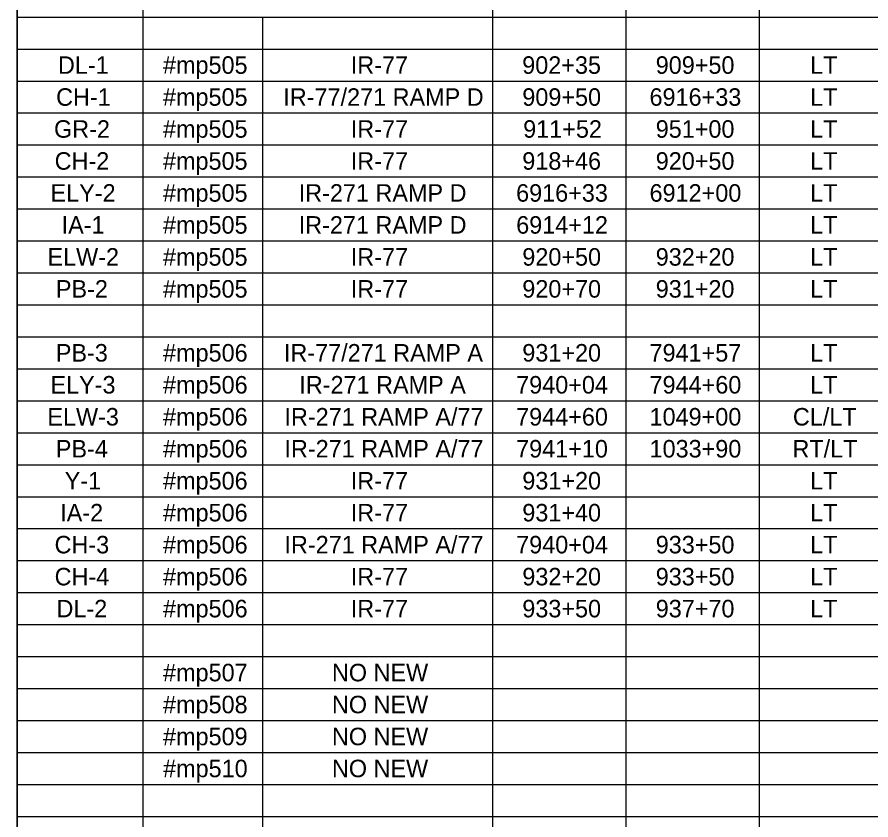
# Model space of a CAD drawing. Extents: x 91011267 to 91022583, y 37007614 to 37014266.
# Drawn here: x 91014537.6 to 91014904.6, y 37008137 to 37008481.9 of the extents above; entities that cross this region are included whole.
import ezdxf

# ---------------------------------------------------------------- set-up
doc = ezdxf.new("R2010")
doc.units = 0
doc.layers.add('SC_Scratch2', color=7, linetype='Continuous')
doc.layers.add('SH_Data', color=7, linetype='Continuous')

msp = doc.modelspace()

# ---------------------------------------------------------------- linework, layer by layer
at = {"layer": 'SC_Scratch2'}
msp.add_lwpolyline([(91014537.63, 37008663.81), (91016062.63, 37008663.81), (91016062.63, 37007613.81), (91014537.63, 37007613.81)], close=True, dxfattribs=at)
at = {"layer": 'SH_Data'}
for p, q in [((91014537.63, 37008498.95), (91014537.63, 37008481.94)), ((91014591.67, 37008498.95), (91014591.67, 37008481.94)), ((91014741.93, 37008498.95), (91014741.93, 37008481.94)), ((91014799.27, 37008498.95), (91014799.27, 37008481.94)), ((91014856.6, 37008498.95), (91014856.6, 37008481.94)), ((91014537.63, 37008481.94), (91014856.6, 37008481.94)), ((91014537.63, 37008481.94), (91014537.63, 37008372.04)), ((91014591.67, 37008481.94), (91014591.67, 37008372.04)), ((91014643.08, 37008481.94), (91014643.08, 37008372.04)), ((91014741.93, 37008481.94), (91014741.93, 37008372.04)), ((91014799.27, 37008481.94), (91014799.27, 37008372.04)), ((91014856.6, 37008481.94), (91014910.64, 37008481.94)), ((91014856.6, 37008481.94), (91014856.6, 37008372.04)), ((91014537.63, 37008468.2), (91014856.6, 37008468.2)), ((91014856.6, 37008468.2), (91014910.64, 37008468.2)), ((91014537.63, 37008454.47), (91014856.6, 37008454.47)), ((91014856.6, 37008454.47), (91014910.64, 37008454.47)), ((91014537.63, 37008440.73), (91014856.6, 37008440.73)), ((91014856.6, 37008440.73), (91014910.64, 37008440.73)), ((91014537.63, 37008426.99), (91014856.6, 37008426.99)), ((91014856.6, 37008426.99), (91014910.64, 37008426.99)), ((91014537.63, 37008413.25), (91014856.6, 37008413.25)), ((91014856.6, 37008413.25), (91014910.64, 37008413.25)), ((91014537.63, 37008399.51), (91014856.6, 37008399.51)), ((91014856.6, 37008399.51), (91014910.64, 37008399.51)), ((91014537.63, 37008385.77), (91014856.6, 37008385.77)), ((91014856.6, 37008385.77), (91014910.64, 37008385.77)), ((91014537.63, 37008372.04), (91014856.6, 37008372.04)), ((91014537.63, 37008372.04), (91014537.63, 37008358.3)), ((91014591.67, 37008372.04), (91014591.67, 37008358.3)), ((91014643.08, 37008372.04), (91014643.08, 37008358.3)), ((91014741.93, 37008372.04), (91014741.93, 37008358.3)), ((91014799.27, 37008372.04), (91014799.27, 37008358.3)), ((91014856.6, 37008372.04), (91014910.64, 37008372.04)), ((91014856.6, 37008372.04), (91014856.6, 37008358.3)), ((91014537.63, 37008358.3), (91014856.6, 37008358.3)), ((91014537.63, 37008358.3), (91014537.63, 37008330.82)), ((91014591.67, 37008358.3), (91014591.67, 37008330.82)), ((91014643.08, 37008358.3), (91014643.08, 37008330.82)), ((91014741.93, 37008358.3), (91014741.93, 37008330.82)), ((91014799.27, 37008358.3), (91014799.27, 37008330.82)), ((91014856.6, 37008358.3), (91014910.64, 37008358.3)), ((91014856.6, 37008358.3), (91014856.6, 37008330.82)), ((91014537.63, 37008344.56), (91014856.6, 37008344.56)), ((91014856.6, 37008344.56), (91014910.64, 37008344.56)), ((91014537.63, 37008330.82), (91014856.6, 37008330.82)), ((91014537.63, 37008330.82), (91014537.63, 37008317.08)), ((91014591.67, 37008330.82), (91014591.67, 37008317.08)), ((91014643.08, 37008330.82), (91014643.08, 37008317.08)), ((91014741.93, 37008330.82), (91014741.93, 37008317.08)), ((91014799.27, 37008330.82), (91014799.27, 37008317.08)), ((91014856.6, 37008330.82), (91014910.64, 37008330.82)), ((91014856.6, 37008330.82), (91014856.6, 37008317.08)), ((91014537.63, 37008317.08), (91014856.6, 37008317.08)), ((91014537.63, 37008317.08), (91014537.63, 37008303.34)), ((91014591.67, 37008317.08), (91014591.67, 37008303.34)), ((91014643.08, 37008317.08), (91014643.08, 37008303.34)), ((91014741.93, 37008317.08), (91014741.93, 37008303.34)), ((91014799.27, 37008317.08), (91014799.27, 37008303.34)), ((91014856.6, 37008317.08), (91014910.64, 37008317.08)), ((91014856.6, 37008317.08), (91014856.6, 37008303.34)), ((91014537.63, 37008303.34), (91014856.6, 37008303.34)), ((91014537.63, 37008303.34), (91014537.63, 37008289.61)), ((91014591.67, 37008303.34), (91014591.67, 37008289.61)), ((91014643.08, 37008303.34), (91014643.08, 37008289.61)), ((91014741.93, 37008303.34), (91014741.93, 37008289.61)), ((91014799.27, 37008303.34), (91014799.27, 37008289.61)), ((91014856.6, 37008303.34), (91014910.64, 37008303.34)), ((91014856.6, 37008303.34), (91014856.6, 37008289.61)), ((91014537.63, 37008289.61), (91014856.6, 37008289.61)), ((91014537.63, 37008289.61), (91014537.63, 37008083.53)), ((91014591.67, 37008289.61), (91014591.67, 37008083.53)), ((91014643.08, 37008289.61), (91014643.08, 37008083.53)), ((91014741.93, 37008289.61), (91014741.93, 37008083.53)), ((91014799.27, 37008289.61), (91014799.27, 37008083.53)), ((91014856.6, 37008289.61), (91014910.64, 37008289.61)), ((91014856.6, 37008289.61), (91014856.6, 37008083.53)), ((91014537.63, 37008275.87), (91014856.6, 37008275.87)), ((91014856.6, 37008275.87), (91014910.64, 37008275.87)), ((91014537.63, 37008262.13), (91014856.6, 37008262.13)), ((91014856.6, 37008262.13), (91014910.64, 37008262.13)), ((91014537.63, 37008248.39), (91014856.6, 37008248.39)), ((91014856.6, 37008248.39), (91014910.64, 37008248.39)), ((91014537.63, 37008234.65), (91014856.6, 37008234.65)), ((91014856.6, 37008234.65), (91014910.64, 37008234.65)), ((91014537.63, 37008220.91), (91014856.6, 37008220.91)), ((91014856.6, 37008220.91), (91014910.64, 37008220.91)), ((91014537.63, 37008207.18), (91014856.6, 37008207.18)), ((91014856.6, 37008207.18), (91014910.64, 37008207.18)), ((91014537.63, 37008193.44), (91014856.6, 37008193.44)), ((91014856.6, 37008193.44), (91014910.64, 37008193.44)), ((91014537.63, 37008179.7), (91014856.6, 37008179.7)), ((91014856.6, 37008179.7), (91014910.64, 37008179.7)), ((91014537.63, 37008165.96), (91014856.6, 37008165.96)), ((91014856.6, 37008165.96), (91014910.64, 37008165.96)), ((91014537.63, 37008152.22), (91014856.6, 37008152.22)), ((91014856.6, 37008152.22), (91014910.64, 37008152.22)), ((91014537.63, 37008138.48), (91014856.6, 37008138.48)), ((91014856.6, 37008138.48), (91014910.64, 37008138.48))]:
    msp.add_line(p, q, dxfattribs=at)

# ---------------------------------------------------------------- texts
for s, height, p in [('DL-1', 7.523, (91014555.2, 37008457.57)), ('#mp505', 7.523, (91014600.35, 37008457.57)), ('IR-77', 7.523, (91014681.07, 37008457.57)), ('902+35', 7.523, (91014754.76, 37008457.57)), ('909+50', 7.523, (91014812.14, 37008457.57)), ('LT', 7.523, (91014878.51, 37008457.57)), ('CH-1', 7.523, (91014554.41, 37008443.83)), ('#mp505', 7.523, (91014600.35, 37008443.83)), ('IR-77/271 RAMP D', 7.5234, (91014652.07, 37008443.83)), ('909+50', 7.523, (91014754.8, 37008443.83)), ('6916+33', 7.523, (91014809.48, 37008443.83)), ('LT', 7.523, (91014878.51, 37008443.83)), ('GR-2', 7.523, (91014553.52, 37008430.1)), ('#mp505', 7.523, (91014600.35, 37008430.1)), ('IR-77', 7.523, (91014681.07, 37008430.1)), ('911+52', 7.523, (91014755.18, 37008430.1)), ('951+00', 7.523, (91014812.14, 37008430.1)), ('LT', 7.523, (91014878.51, 37008430.1)), ('CH-2', 7.523, (91014553.79, 37008416.36)), ('#mp505', 7.523, (91014600.35, 37008416.36)), ('IR-77', 7.523, (91014681.07, 37008416.36)), ('918+46', 7.523, (91014754.79, 37008416.36)), ('920+50', 7.523, (91014812.14, 37008416.36)), ('LT', 7.523, (91014878.51, 37008416.36)), ('ELY-2', 7.523, (91014552.02, 37008402.62)), ('#mp505', 7.523, (91014600.35, 37008402.62)), ('IR-271 RAMP D', 7.5234, (91014658.69, 37008402.62)), ('6916+33', 7.523, (91014752.14, 37008402.62)), ('6912+00', 7.523, (91014809.49, 37008402.62)), ('LT', 7.523, (91014878.51, 37008402.62)), ('IA-1', 7.523, (91014556.79, 37008388.88)), ('#mp505', 7.523, (91014600.35, 37008388.88)), ('IR-271 RAMP D', 7.5234, (91014658.69, 37008388.88)), ('6914+12', 7.523, (91014752.18, 37008388.88)), ('LT', 7.523, (91014878.51, 37008388.88)), ('ELW-2', 7.523, (91014550.7, 37008375.14)), ('#mp505', 7.523, (91014600.35, 37008375.14)), ('IR-77', 7.523, (91014681.07, 37008375.14)), ('920+50', 7.523, (91014754.8, 37008375.14)), ('932+20', 7.523, (91014812.14, 37008375.14)), ('LT', 7.523, (91014878.51, 37008375.14)), ('PB-2', 7.523, (91014554.31, 37008361.4)), ('#mp505', 7.523, (91014600.35, 37008361.4)), ('IR-77', 7.523, (91014681.07, 37008361.4)), ('920+70', 7.523, (91014754.8, 37008361.4)), ('931+20', 7.523, (91014812.14, 37008361.4)), ('LT', 7.523, (91014878.51, 37008361.4)), ('PB-3', 7.523, (91014554.28, 37008333.93)), ('#mp506', 7.523, (91014600.38, 37008333.93)), ('IR-77/271 RAMP A', 7.5234, (91014652.33, 37008333.93)), ('931+20', 7.523, (91014754.8, 37008333.93)), ('7941+57', 7.523, (91014809.48, 37008333.93)), ('LT', 7.523, (91014878.51, 37008333.93)), ('ELY-3', 7.523, (91014551.98, 37008320.19)), ('#mp506', 7.523, (91014600.38, 37008320.19)), ('IR-271 RAMP A', 7.5234, (91014658.95, 37008320.19)), ('7940+04', 7.523, (91014752.16, 37008320.19)), ('7944+60', 7.523, (91014809.49, 37008320.19)), ('LT', 7.523, (91014878.51, 37008320.19)), ('ELW-3', 7.523, (91014550.66, 37008306.45)), ('#mp506', 7.523, (91014600.38, 37008306.45)), ('IR-271 RAMP A/77', 7.5234, (91014652.56, 37008306.45)), ('7944+60', 7.523, (91014752.15, 37008306.45)), ('1049+00', 7.523, (91014809.49, 37008306.45)), ('CL/LT', 7.523, (91014871.1, 37008306.45)), ('IR-271 RAMP A/77', 7.5234, (91014652.56, 37008292.71)), ('RT/LT', 7.523, (91014870.92, 37008292.71)), ('PB-4', 7.523, (91014554.29, 37008292.71)), ('#mp506', 7.523, (91014600.38, 37008292.71)), ('7941+10', 7.523, (91014752.15, 37008292.71)), ('1033+90', 7.523, (91014809.49, 37008292.71)), ('Y-1', 7.523, (91014558.11, 37008278.97)), ('#mp506', 7.523, (91014600.38, 37008278.97)), ('IR-77', 7.523, (91014681.07, 37008278.97)), ('931+20', 7.523, (91014754.8, 37008278.97)), ('LT', 7.523, (91014878.51, 37008278.97)), ('IA-2', 7.523, (91014556.17, 37008265.24)), ('#mp506', 7.523, (91014600.38, 37008265.24)), ('IR-77', 7.523, (91014681.07, 37008265.24)), ('931+40', 7.523, (91014754.8, 37008265.24)), ('LT', 7.523, (91014878.51, 37008265.24)), ('CH-3', 7.523, (91014553.75, 37008251.5)), ('#mp506', 7.523, (91014600.38, 37008251.5)), ('IR-271 RAMP A/77', 7.5234, (91014652.56, 37008251.5)), ('7940+04', 7.523, (91014752.16, 37008251.5)), ('933+50', 7.523, (91014812.14, 37008251.5)), ('LT', 7.523, (91014878.51, 37008251.5)), ('CH-4', 7.523, (91014553.77, 37008237.76)), ('#mp506', 7.523, (91014600.38, 37008237.76)), ('IR-77', 7.523, (91014681.07, 37008237.76)), ('932+20', 7.523, (91014754.8, 37008237.76)), ('933+50', 7.523, (91014812.14, 37008237.76)), ('LT', 7.523, (91014878.51, 37008237.76)), ('DL-2', 7.523, (91014554.58, 37008224.02)), ('#mp506', 7.523, (91014600.38, 37008224.02)), ('IR-77', 7.523, (91014681.07, 37008224.02)), ('933+50', 7.523, (91014754.8, 37008224.02)), ('937+70', 7.523, (91014812.14, 37008224.02)), ('LT', 7.523, (91014878.51, 37008224.02)), ('#mp507', 7.523, (91014600.38, 37008196.54)), ('NO NEW', 7.523, (91014672.97, 37008196.54)), ('#mp508', 7.523, (91014600.37, 37008182.81)), ('NO NEW', 7.523, (91014672.97, 37008182.81)), ('#mp509', 7.523, (91014600.37, 37008169.07)), ('NO NEW', 7.523, (91014672.97, 37008169.07)), ('#mp510', 7.523, (91014600.39, 37008155.33)), ('NO NEW', 7.523, (91014672.97, 37008155.33))]:
    msp.add_text(s, height=height, dxfattribs=at).set_placement(p)

doc.saveas('drawing.dxf')
